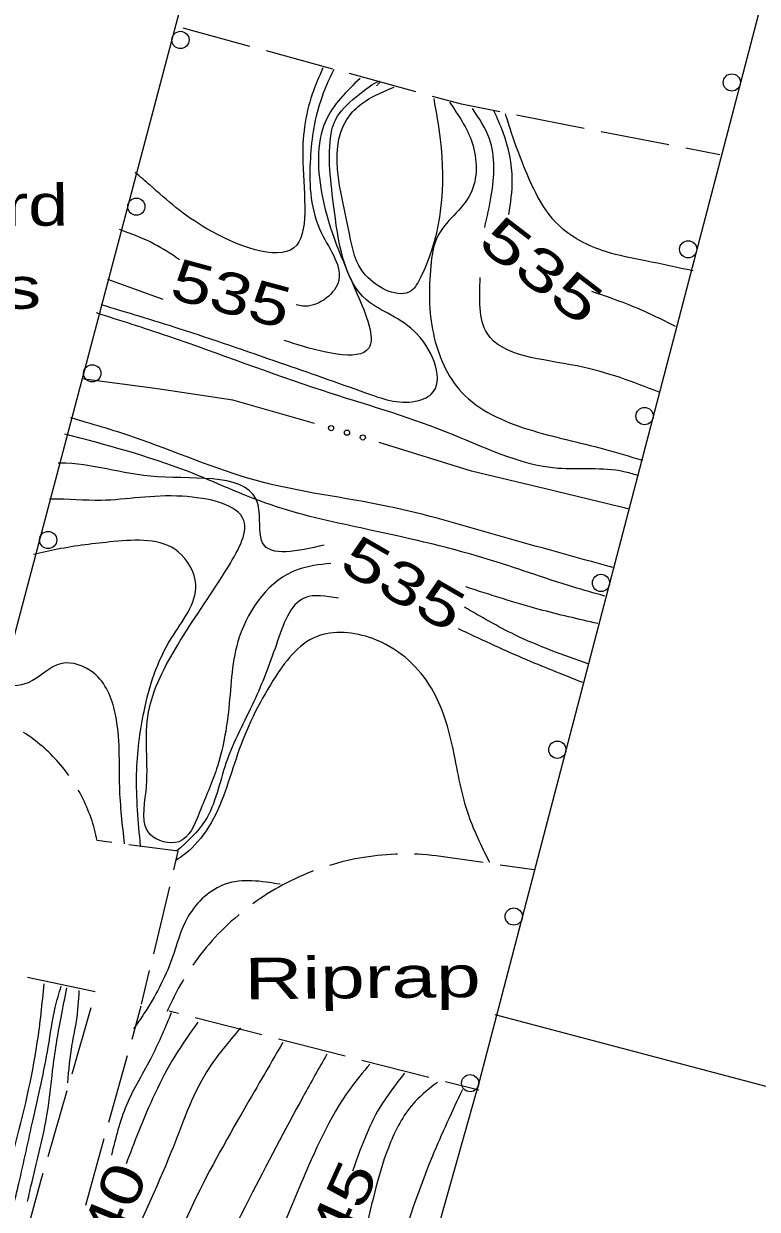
# Model space of a CAD drawing. Extents: x 2361708 to 2370558, y 6977955 to 6991887.
# Drawn here: x 2366031.4 to 2366116.6, y 6983300.7 to 6983438.2 of the extents above; entities that cross this region are included whole.
import ezdxf
from ezdxf.enums import TextEntityAlignment as Align

# ---------------------------------------------------------------- set-up
doc = ezdxf.new("R2010")
doc.units = 0
doc.header["$LTSCALE"] = 1.9
for name, color, linetype, lineweight in [('25', 7, 'Continuous', 25), ('31', 7, 'Continuous', 13), ('35', 7, 'Continuous', 13), ('4', 7, 'Continuous', 25), ('8', 7, 'Continuous', 13), ('9', 7, 'Continuous', 13)]:
    doc.layers.add(name, color=color, linetype=linetype, lineweight=lineweight)

msp = doc.modelspace()

# ---------------------------------------------------------------- linework, layer by layer
at = {"layer": '25'}
for points in [[(2366065.196, 6983391.852), (2366055.72, 6983394.552), (2366046.968, 6983395.849), (2366038.196, 6983396.995)], [(2366101.683, 6983381.899), (2366101.151, 6983382.044), (2366100.61, 6983382.179), (2366092.01, 6983384.257), (2366083.4, 6983386.285), (2366072.708, 6983389.623)]]:
    msp.add_lwpolyline(points, dxfattribs=at)
for centre in [(2366067.117, 6983391.301), (2366068.964, 6983390.775), (2366070.801, 6983390.218)]:
    msp.add_circle(centre, 0.3, dxfattribs=at)
at = {"layer": '31', "lineweight": 25}
for points in [[(2366067.425, 6983432.905), (2366065.871, 6983429.19), (2366064.688, 6983422.119), (2366066.016, 6983413.911), (2366067.921, 6983408.169), (2366063.837, 6983405.45), (2366063.075, 6983405.612)], [(2366087.757, 6983416.068), (2366088.149, 6983420.082), (2366087.086, 6983425.582), (2366086.012, 6983428.082)], [(2366049.545, 6983410.824), (2366046.597, 6983412.646), (2366042.551, 6983414.318)], [(2366107.081, 6983403.101), (2366102.199, 6983405.385), (2366097.382, 6983407.129)], [(2366067.071, 6983375.599), (2366063.188, 6983374.862), (2366056.462, 6983367.038), (2366055.25, 6983358.816), (2366053.837, 6983351.792), (2366051.855, 6983346.762), (2366049.437, 6983343.32), (2366046.119, 6983344.158), (2366045.641, 6983349.154), (2366045.934, 6983358.357), (2366049.32, 6983366.159), (2366054.977, 6983374.894), (2366057.003, 6983380.563), (2366049.876, 6983383.386), (2366040.42, 6983382.916), (2366034.638, 6983383.061), (2366034.438, 6983383.059)], [(2366096.943, 6983363.943), (2366088.451, 6983367.312), (2366082.59, 6983370.537)], [(2366030.354, 6983301.506), (2366030.884, 6983303.661), (2366032.533, 6983311.097), (2366034.293, 6983319.485), (2366035.1, 6983324.082), (2366035.796, 6983326.559)], [(2366051.647, 6983322.38), (2366048.994, 6983318.454), (2366044.767, 6983309.674), (2366043.333, 6983305.95)], [(2366075.625, 6983316.458), (2366072.772, 6983312.49), (2366069.612, 6983305.12)]]:
    msp.add_spline(points, degree=3, dxfattribs=at)
at = {"layer": '35'}
msp.add_line((2366047.639, 6983406.206), (2366041.197, 6983408.535), dxfattribs=at)
for points in [[(2366040.404, 6983405.636), (2366049.441, 6983402.862), (2366061.209, 6983398.885), (2366071.113, 6983395.399), (2366076.892, 6983394.413), (2366078.745, 6983395.241), (2366077.109, 6983402.186), (2366071.23, 6983406.16), (2366067.404, 6983417.234), (2366067.222, 6983425.883), (2366068.648, 6983428.457), (2366072.611, 6983431.265), (2366072.384, 6983430.992)], [(2366066.164, 6983433.093), (2366064.933, 6983430.021), (2366063.838, 6983422.11), (2366062.802, 6983412.2), (2366052.7, 6983414.424), (2366046.112, 6983419.462), (2366044.398, 6983420.936)], [(2366070.476, 6983431.864), (2366066.502, 6983426.956), (2366066.116, 6983418.082), (2366070.154, 6983406.85), (2366071.493, 6983400.562), (2366062.728, 6983401.129), (2366061.684, 6983401.479)], [(2366079.028, 6983429.516), (2366079.773, 6983424.802), (2366077.535, 6983408.85), (2366076.41, 6983407.24), (2366071.113, 6983409.049), (2366069.257, 6983413.842), (2366069.434, 6983427.784), (2366071.121, 6983429.24), (2366074.425, 6983430.852)], [(2366080.842, 6983429.103), (2366083.477, 6983424.407), (2366083.294, 6983418.485), (2366079.431, 6983413.439), (2366078.683, 6983410.081), (2366078.988, 6983402.254), (2366082.283, 6983395.435), (2366089.954, 6983391.177), (2366098.846, 6983388.872), (2366103.249, 6983387.564)], [(2366084.941, 6983414.581), (2366085.706, 6983418.258), (2366085.483, 6983424.857), (2366083.52, 6983428.378)], [(2366109.13, 6983409.531), (2366103.619, 6983410.699), (2366098.948, 6983411.784), (2366093.488, 6983414.873), (2366089.719, 6983421.107), (2366088.067, 6983425.511), (2366087.366, 6983427.735)], [(2366105.174, 6983395.463), (2366095.654, 6983398.512), (2366085.218, 6983402.293), (2366084.416, 6983408.766)], [(2366039.853, 6983404.691), (2366048.129, 6983402), (2366066.09, 6983395.681), (2366080.356, 6983390.916), (2366093.417, 6983386.671), (2366101.091, 6983386.274), (2366102.625, 6983385.858)], [(2366099.797, 6983375.14), (2366086.732, 6983378.776), (2366073.688, 6983382.222), (2366058.479, 6983385.208), (2366044.2, 6983390.252), (2366036.868, 6983392.503)], [(2366098.889, 6983371.812), (2366095.188, 6983372.877), (2366085.117, 6983376.141), (2366070.572, 6983379.713), (2366060.146, 6983382.383), (2366050.438, 6983386.292), (2366036.217, 6983390.606)], [(2366066.311, 6983377.732), (2366059.177, 6983377.994), (2366058.646, 6983382.399), (2366046.975, 6983385.648), (2366035.639, 6983387.24), (2366035.459, 6983387.239)], [(2366045.012, 6983342.827), (2366044.552, 6983351.174), (2366045.413, 6983358.442), (2366048.573, 6983366.902), (2366051.413, 6983373.16), (2366049.367, 6983376.961), (2366041.876, 6983378.13), (2366035.364, 6983377.237), (2366032.57, 6983376.621)], [(2366098.059, 6983368.624), (2366091.273, 6983370.269), (2366082.768, 6983372.879)], [(2366067.959, 6983371.557), (2366064.069, 6983371.62), (2366060.77, 6983366.209), (2366058.153, 6983359.573), (2366054.921, 6983352.432), (2366052.504, 6983345.769), (2366049.228, 6983342.248)], [(2366085.532, 6983340.893), (2366082.967, 6983346.719), (2366081.203, 6983354.392), (2366078.515, 6983361.537), (2366071.965, 6983366.875), (2366065.412, 6983367.103), (2366060.4, 6983362.055), (2366056.271, 6983353.485), (2366052.911, 6983345.013), (2366050.161, 6983341.896), (2366049.158, 6983341.187)], [(2366096.314, 6983361.786), (2366089.417, 6983364.591), (2366081.884, 6983368.019)], [(2366043.159, 6983343.08), (2366042.587, 6983349.675), (2366042.075, 6983358.22), (2366039.551, 6983362.897), (2366035.86, 6983363.992), (2366031.961, 6983361.764), (2366028.665, 6983361.363)], [(2366061.215, 6983338.382), (2366054.844, 6983338.401), (2366050.55, 6983334.67), (2366048.637, 6983329.721), (2366045.407, 6983323.38), (2366044.204, 6983321.609)], [(2366028.789, 6983302.111), (2366030.325, 6983307.676), (2366033.029, 6983319.992), (2366033.823, 6983326.84)], [(2366031.904, 6983301.591), (2366032.412, 6983303.886), (2366034.187, 6983311.813), (2366034.809, 6983316.779), (2366035.781, 6983322.939), (2366036.468, 6983326.375)], [(2366036.563, 6983315.346), (2366037.071, 6983319.821), (2366037.575, 6983322.516), (2366037.901, 6983326.079)], [(2366048.576, 6983323.491), (2366046.343, 6983318.469), (2366043.378, 6983312.761), (2366041.623, 6983306.944)], [(2366056.613, 6983321.717), (2366052.711, 6983316.669), (2366048.541, 6983307.269), (2366043.269, 6983294.799), (2366039.319, 6983282.12), (2366035.271, 6983271.361), (2366030.523, 6983258.595), (2366026.809, 6983249.52), (2366023.057, 6983239.223), (2366018.66, 6983226.231)], [(2366061.51, 6983320.013), (2366056.679, 6983311.687), (2366050.441, 6983299.917), (2366044.326, 6983283.478), (2366038.72, 6983267.374), (2366031.887, 6983246.568), (2366025.607, 6983227.687), (2366019.349, 6983207.486), (2366013.561, 6983195.691), (2366010.608, 6983188.592), (2366007.153, 6983178.659)], [(2366066.623, 6983318.692), (2366063.88, 6983313.756), (2366057.612, 6983301.905), (2366050.674, 6983286.969), (2366044.783, 6983269.152), (2366038.769, 6983253.734), (2366031.007, 6983229.818), (2366026.046, 6983212.001), (2366019.806, 6983195.211), (2366014.789, 6983182.262), (2366009.223, 6983168.138), (2366005.12, 6983157.908), (2366001.182, 6983147.181), (2365997.938, 6983139.16)], [(2366071.604, 6983317.529), (2366069.321, 6983314.668), (2366063.577, 6983303.542), (2366057.507, 6983288.744), (2366050.633, 6983269.218), (2366043.732, 6983251.361), (2366037.633, 6983233.362), (2366031.613, 6983213.374), (2366020.934, 6983183.801), (2366013.313, 6983161.807), (2366006.877, 6983143.555), (2366000.217, 6983128.801), (2365995.258, 6983116.063), (2365991.519, 6983106.497), (2365989.256, 6983099.425), (2365987.133, 6983094.475)], [(2366079.455, 6983315.404), (2366076.886, 6983313.19), (2366074.02, 6983308.462), (2366070.981, 6983297.912), (2366064.742, 6983279.872), (2366058.234, 6983258.649), (2366052.396, 6983239.473), (2366044.947, 6983218.291), (2366036.851, 6983194.762), (2366029.596, 6983171.012), (2366021.992, 6983147.249), (2366012.028, 6983123.503), (2366004.794, 6983108.143), (2365997.641, 6983093.655), (2365991.052, 6983076.791), (2365987.974, 6983068.111)], [(2365996.518, 6983068.833), (2366001.86, 6983082.284), (2366010.317, 6983099.385), (2366023.676, 6983126.934), (2366034.104, 6983153.475), (2366038.222, 6983168.314), (2366043.934, 6983189.16), (2366050.836, 6983212.197), (2366058.008, 6983236.116), (2366065.235, 6983261.646), (2366071.126, 6983281.663), (2366074.304, 6983293.364), (2366078.886, 6983306.818), (2366082.402, 6983314.632)], [(2366011.561, 6983069.626), (2366020.313, 6983086.26), (2366035.878, 6983115.209), (2366059.611, 6983153.838), (2366077.141, 6983181.255), (2366102.675, 6983224.061), (2366117.648, 6983250.064), (2366130.881, 6983277.182), (2366138.805, 6983294.698), (2366144.228, 6983306.96)]]:
    msp.add_spline(points, degree=3, dxfattribs=at)
at = {"layer": '4'}
for points in [[(2366040.402, 6983171.625), (2366048.426, 6983194.253), (2366065.604, 6983249.159), (2366084.392, 6983315.681), (2366118.878, 6983447.566), (2366137.081, 6983520.962), (2366154.16, 6983594.659), (2366157.652, 6983617.623)], [(2366086.199, 6983581.791), (2366079.927, 6983559.96), (2366066.999, 6983506.035), (2366056.325, 6983465.491), (2366020.405, 6983329.793), (2366016.933, 6983320.479)]]:
    msp.add_lwpolyline(points, dxfattribs=at)
for centre in [(2366049.638, 6983436.323), (2366113.615, 6983431.39), (2366044.521, 6983416.989), (2366108.555, 6983412.04), (2366039.403, 6983397.655), (2366103.496, 6983392.691), (2366034.285, 6983378.321), (2366098.436, 6983373.341), (2366093.376, 6983353.992), (2366088.317, 6983334.642), (2366083.25, 6983315.315)]:
    msp.add_circle(centre, 1, dxfattribs=at)
at = {"layer": '8'}
for p, q in [((2366057.68, 6983435.573), (2366049.959, 6983437.679)), ((2366067.325, 6983432.944), (2366059.605, 6983435.051)), ((2366076.971, 6983430.306), (2366069.251, 6983432.413)), ((2366096.502, 6983426.062), (2366088.647, 6983427.597)), ((2366106.321, 6983424.145), (2366098.466, 6983425.68)), ((2366112.212, 6983423.001), (2366108.284, 6983423.764)), ((2366090.691, 6983340.042), (2366086.735, 6983340.614)), ((2366046.531, 6983330.322), (2366048.397, 6983338.099)), ((2366039.722, 6983325.926), (2366031.886, 6983327.552)), ((2366045.126, 6983324.488), (2366046.059, 6983328.377)), ((2366037.063, 6983316.401), (2366039.29, 6983324.082)), ((2366045.059, 6983324.247), (2366043.985, 6983320.397)), ((2366049.397, 6983323.388), (2366048.315, 6983323.668)), ((2366059.081, 6983320.91), (2366051.332, 6983322.897)), ((2366068.765, 6983318.442), (2366061.016, 6983320.419)), ((2366043.444, 6983318.471), (2366041.297, 6983310.77)), ((2366078.449, 6983315.974), (2366070.7, 6983317.951)), ((2366084.264, 6983314.49), (2366080.384, 6983315.483)), ((2366034.274, 6983306.794), (2366036.501, 6983314.475)), ((2366040.755, 6983308.845), (2366038.608, 6983301.135))]:
    msp.add_line(p, q, dxfattribs=at)
for points in [[(2366086.683, 6983427.978), (2366082.245, 6983428.856), (2366078.896, 6983429.774)], [(2366036.704, 6983350.989), (2366036.582, 6983351.158), (2366036.38, 6983351.426), (2366036.167, 6983351.694), (2366035.954, 6983351.962), (2366035.742, 6983352.22), (2366035.519, 6983352.478), (2366035.297, 6983352.725), (2366035.065, 6983352.973), (2366034.833, 6983353.221), (2366034.59, 6983353.468), (2366034.348, 6983353.706), (2366034.096, 6983353.934), (2366033.844, 6983354.162), (2366033.592, 6983354.389), (2366033.329, 6983354.607), (2366033.067, 6983354.814), (2366032.805, 6983355.032), (2366032.533, 6983355.23), (2366032.261, 6983355.437), (2366031.979, 6983355.634), (2366031.698, 6983355.821), (2366031.415, 6983356.009)], [(2366041.678, 6983343.226), (2366039.976, 6983343.449), (2366039.903, 6983343.779), (2366039.83, 6983344.108), (2366039.746, 6983344.438), (2366039.663, 6983344.766), (2366039.57, 6983345.096), (2366039.477, 6983345.425), (2366039.374, 6983345.744), (2366039.26, 6983346.063), (2366039.148, 6983346.382), (2366039.024, 6983346.7), (2366038.902, 6983347.02), (2366038.768, 6983347.328), (2366038.635, 6983347.647), (2366038.493, 6983347.946), (2366038.34, 6983348.254), (2366038.187, 6983348.563), (2366038.034, 6983348.862), (2366037.871, 6983349.16), (2366037.78, 6983349.309)], [(2366048.869, 6983340.044), (2366049.388, 6983342.209), (2366043.66, 6983342.965)], [(2366074.812, 6983341.871), (2366074.592, 6983341.869), (2366074.072, 6983341.844), (2366073.543, 6983341.809), (2366073.023, 6983341.774), (2366072.504, 6983341.719), (2366071.984, 6983341.655), (2366071.455, 6983341.579), (2366070.936, 6983341.504), (2366070.417, 6983341.419), (2366069.907, 6983341.324), (2366069.389, 6983341.21), (2366068.88, 6983341.094), (2366068.371, 6983340.97), (2366067.861, 6983340.835), (2366067.353, 6983340.69), (2366066.944, 6983340.576)], [(2366084.752, 6983340.896), (2366079.314, 6983341.684), (2366078.794, 6983341.739), (2366078.273, 6983341.794), (2366077.743, 6983341.829), (2366077.223, 6983341.864), (2366076.812, 6983341.88)], [(2366065.05, 6983339.928), (2366064.871, 6983339.856), (2366064.383, 6983339.662), (2366063.895, 6983339.457), (2366063.417, 6983339.242), (2366062.939, 6983339.028), (2366062.461, 6983338.793), (2366061.993, 6983338.559), (2366061.526, 6983338.315), (2366061.068, 6983338.06), (2366060.61, 6983337.806), (2366060.163, 6983337.531), (2366059.716, 6983337.257), (2366059.268, 6983336.973), (2366058.831, 6983336.679), (2366058.404, 6983336.385), (2366058.036, 6983336.121)], [(2366056.468, 6983334.886), (2366056.329, 6983334.775), (2366055.932, 6983334.431), (2366055.536, 6983334.087), (2366055.149, 6983333.724), (2366054.773, 6983333.36), (2366054.396, 6983332.996), (2366054.029, 6983332.623), (2366053.673, 6983332.239), (2366053.317, 6983331.846), (2366052.97, 6983331.453), (2366052.634, 6983331.05), (2366052.298, 6983330.646), (2366051.972, 6983330.233), (2366051.656, 6983329.81), (2366051.35, 6983329.387), (2366051.073, 6983329.005)], [(2366049.98, 6983327.324), (2366049.901, 6983327.193), (2366049.645, 6983326.741), (2366049.38, 6983326.288), (2366049.134, 6983325.825), (2366048.898, 6983325.354), (2366048.663, 6983324.881), (2366048.437, 6983324.409), (2366048.222, 6983323.927), (2366048.085, 6983323.616)], [(2366031.596, 6983297.147), (2366033.567, 6983304.377), (2366033.713, 6983304.868)]]:
    msp.add_lwpolyline(points, dxfattribs=at)
at = {"layer": '9'}
msp.add_line((2366154.246, 6983305.185), (2366086.15, 6983323.258), dxfattribs=at)

# ---------------------------------------------------------------- texts
at = {"layer": '31'}
for s, rotation, width, p in [(' 535 ', 322.498, 1.45, (2366090.099, 6983407.698)), (' 535 ', 344.837, 1.3, (2366054.917, 6983404.595)), (' 535 ', 330.002, 1.4, (2366074.335, 6983371.204)), (' 540 ', 67.705, 1.3, (2366043.28, 6983298.306)), (' 545 ', 65.679, 1.35, (2366069.684, 6983298.24))]:
    msp.add_text(s, height=4.8, rotation=rotation, dxfattribs=dict(at, width=width)).set_placement(p, align=Align.CENTER)
at = {"layer": '4'}
for s, width, p in [('Guard', 1.3, (2366013.437, 6983414.581)), ('Rails', 1.4, (2366013.529, 6983404.981))]:
    msp.add_text(s, height=4.8, rotation=0.545, dxfattribs=dict(at, width=width)).set_placement(p)
at = {"layer": '8', "width": 1.45}
msp.add_text('Riprap', height=4.8, rotation=0.545, dxfattribs=at).set_placement((2366057.082, 6983325.041))

doc.saveas('drawing.dxf')
